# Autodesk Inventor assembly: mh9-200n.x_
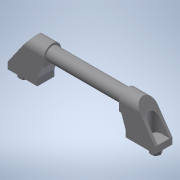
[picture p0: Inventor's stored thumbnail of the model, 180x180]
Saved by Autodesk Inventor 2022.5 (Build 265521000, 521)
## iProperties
Part Number: mh9-200n.x_
Material: 一般
Document SubType Name: Assembly
Designer: ImaoCorp
Sending System: SOLIDWORKS 2017-2017317
MC: AMD64
MC_MODEL: Intel64 Family 6 Model 60 Stepping 3, GenuineIntel
OS: Windows_NT
FRU: Parasolid Version 29.0, build 201,  4-17-2017
FORMAT: text
GUISE: transmit
KEY: mh9-200n
FILE: mh9-200n.x_t
DATE: Fri Jul 26 11:47:08 2019
Author: ImaoCorp
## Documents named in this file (4)
- X:\14_SW2022-Inv2022\00_全2023-1023新製品(TCC)まで\m\mh9-200n\MH9-200N.iam
- X:\14_SW2022-Inv2022\00_全2023-1023新製品(TCC)まで\m\mh9-200n\mh9-200n_01.ipt
- X:\14_SW2022-Inv2022\00_全2023-1023新製品(TCC)まで\m\mh9-200n\mh9-200n_02.ipt
- X:\14_SW2022-Inv2022\00_全2023-1023新製品(TCC)まで\m\mh9-200n\mh9-200n_03.ipt
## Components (3 placed, 3 different names)
1. mh9-200n_01
2. mh9-200n_02
3. mh9-200n_03
